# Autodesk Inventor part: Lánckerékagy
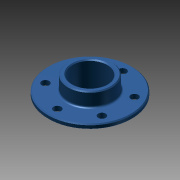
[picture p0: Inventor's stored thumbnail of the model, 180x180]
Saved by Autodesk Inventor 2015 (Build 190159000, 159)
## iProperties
Created: 2013-02
Part Number: Lánckerékagy
Material: Generic
Document SubType Name: Modeling
Designer: Marci
Density: 1 g/cm^3
Appearance: Sky Blue Dark
Author: Marci
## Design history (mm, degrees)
sketch "Sketch1"
  geometry: C1 r 18.5 at (0, 0); C2 r 23.5 at (0, 0); 1 further point
  constraints: 2 centre point, 2 coincident
  dimensions: "d0" = 37 diameter of C1
extrude "Extrusion1" new body sketch "Sketch1" distance "d2" = 30; taper "d3" = 0 deg
workplane "Work Plane1"
sketch "Sketch2"
  geometry: C1 r 45 at (0, 0); C2 r 23.5 at (0, 0); C3 r 4 at (0, 35); C4 r 4 at (-30.311, 17.5); C5 r 4 at (-30.311, -17.5); C6 r 4 at (0, -35); C7 r 4 at (30.311, -17.5); C8 r 4 at (30.311, 17.5); 1 further point
  constraints: 8 centre point, 1 coincident, 13 other
  dimensions: "d6" = 90 diameter of C1; "d7" = 47 diameter of C2; "d8" = 8 diameter of C3; "d11" = 360 deg dimension on point (0, 0) C3.centre (derived)
extrude "Extrusion2" join sketch "Sketch2" distance "d13" = 5; taper "d14" = 0 deg
fillet "Fillet1" dims "d15" = 2
chamfer "Chamfer1" distance "d16" = 1; stored, may be unused: second distance "d17" = 2, angle "d18" = 45 deg
body "Solid1"
other parameters: "d4" = -15
